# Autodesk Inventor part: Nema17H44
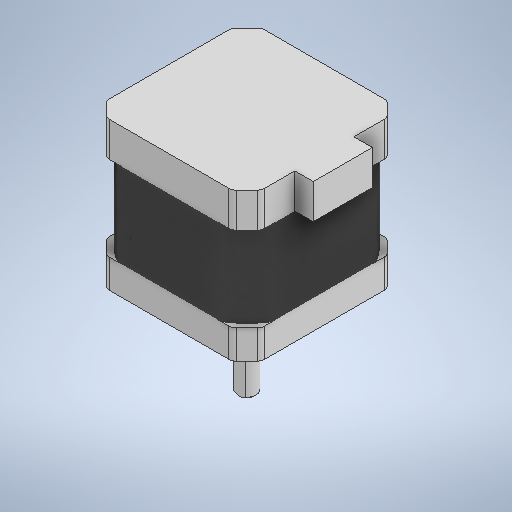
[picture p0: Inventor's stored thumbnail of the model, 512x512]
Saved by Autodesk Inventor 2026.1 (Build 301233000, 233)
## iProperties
Created: 2025-12
Part Number: Nema17H44
Material: Типовые
Document SubType Name: Modeling
Designer: Yury Melnikov
Density: 1 g/cm^3
Appearance: По умолчанию
Author: Yury Melnikov
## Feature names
1. Выдавливание1 [Extrusion]
2. Выдавливание2 [Extrusion]
3. Выдавливание3 [Extrusion]
4. Сопряжение2 [Fillet]
5. Сдвиг1
6. Круговой массив1 [Circular Pattern]
7. Выдавливание4 [Extrusion]
8. Сопряжение3 [Fillet]
9. Выдавливание5 [Extrusion]
10. Фаска2 [Chamfer]
11. Выдавливание6 [Extrusion]
12. Выдавливание7 [Extrusion]
13. Выдавливание8 [Extrusion]
14. Фаска3 [Chamfer]
## Parameters: d0 = 42 mm, d1 = 42 mm, d2 = 4 mm, d3 = 4 mm, d4 = 4 mm, d5 = 4 mm, d6 = 4 mm, d7 = 4 mm, d8 = 4 mm, d9 = 4 mm, d10 = 2 mm, d11 = 9.4 mm, d12 = 0, d14 = 42 mm, d15 = 7 mm, d16 = 7 mm, d17 = 7 mm, d18 = 7 mm, d19 = 7 mm, d20 = 7 mm, d21 = 7 mm, d22 = 7 mm, d26 = 360 deg, d28 = 22.9 mm, d29 = 0, d30 = 7.8 mm, d31 = 0, d32 = 3 mm, d35 = 0.229 mm, d38 = 0.458 mm, d43 = -11.5 mm, d44 = -15.75 mm, d45 = 0, d46 = 0, d48 = 360 deg, d50 = 22 mm, d51 = 1.9 mm, d52 = 0, d53 = 1 mm, d54 = 9 mm, d55 = 5 mm, d57 = 26.3 mm, d58 = 0, d62 = 0.6 mm, d63 = 2 mm, d64 = 45 deg, d65 = 4.4 mm, d66 = 22.1 mm, d67 = 0, d68 = 5 mm, d69 = 16 mm, d70 = 22.1 mm, d71 = 0, d74 = 30.5 mm, d77 = 30.5 mm, d80 = 2.6 mm, d82 = 0, d83 = 0.6 mm, d84 = 2 mm, d85 = 45 deg
